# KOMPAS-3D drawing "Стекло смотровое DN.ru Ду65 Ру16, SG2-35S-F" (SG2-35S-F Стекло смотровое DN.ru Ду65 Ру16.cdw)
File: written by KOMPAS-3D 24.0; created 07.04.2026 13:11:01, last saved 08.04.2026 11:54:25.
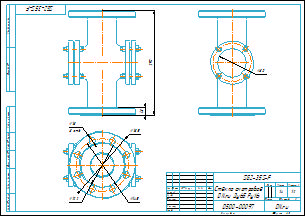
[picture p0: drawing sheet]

Document properties: Автор: Main; Форматы листов документа: A3; Полное имя файла: SG2-35S-F Стекло смотровое DN.ru Ду65 Ру16.m3d; Масса: 14; Наименование: Стекло смотровое DN.ru Ду65 Ру16; Количество листов документа: 1; Примечание: D500-00097

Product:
- Body: Тело 1  | qty 1
    Масса: 13.01185
- Part/product: Стекло смотровое DN.ru Ду65 Ру16  | designation SG2-35S-F
    Масса: 14
    Раздел спецификации: Прочие изделия
    Примечание: D500-00097

Views: Вид 1, Снизу, Проекционный вид 2
Referenced files in D:\DN.ru Аутсерс\Стекло смотровое DN.ru\Стекло смотровое DN.ru SG2-34G-F тип В ГОСТ 21836-2021 Ду100 Ру16, углеродистая сталь, фланцевое\: SG2-34G-F тип В Стекло смотровое DN.ru Ду100 Ру16.m3d, SG2-34G-F тип ВСтекло смотровое DN.ru Ду100 Ру16.cdw
Referenced files in D:\DN.ru Аутсерс\Стекло смотровое DN.ru\SG2-35S-F Стекло смотровое DN.ru Ду65 Ру16\: SG2-35S-F Стекло смотровое DN.ru Ду65 Ру16.m3d
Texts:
  SG2-35S-F
  Стекло смотровое
  DN.ru Ду65 Ру16
  Стекло смотровое DN.ru Ду65 Ру16
  SG2-35S-F Стекло смотровое DN.ru Ду65 Ру16
Dimensions and other numbers on the sheet: 0; 3; 2; 4; 290; 18; 8 отв.; 185; 145; 122; 1:2; 1; 14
